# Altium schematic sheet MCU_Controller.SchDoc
size A4; Organization: Q-Tech Design; Address1: Da Nang City; Address2: Viet Nam; DocumentNumber: 2; SheetNumber: 2; SheetTotal: 7
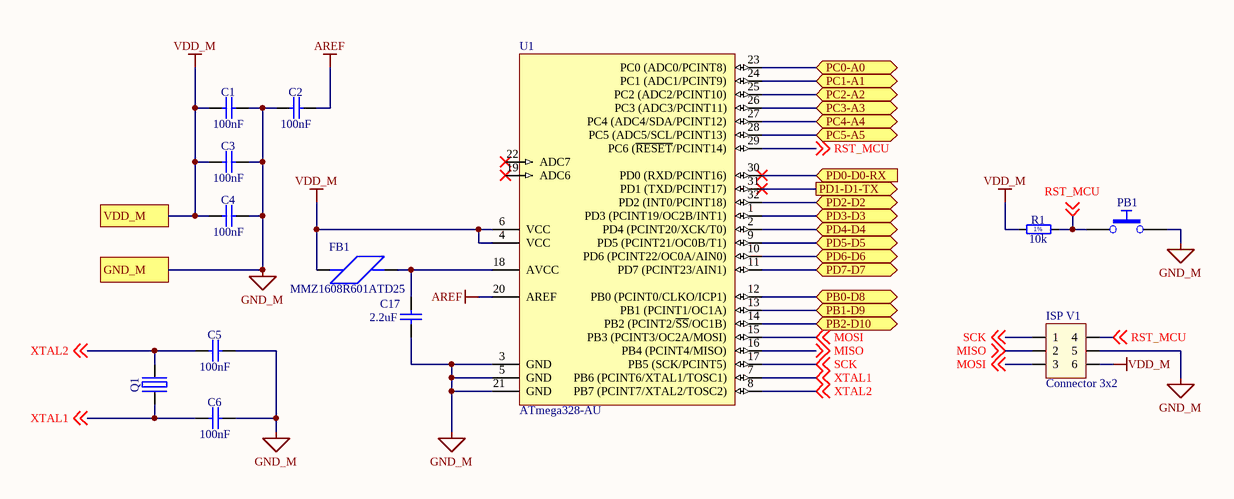
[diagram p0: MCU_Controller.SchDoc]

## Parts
C1  100nF  [CAPC1608X87N]
C2  100nF  [CAPC1608X87N]
C3  100nF  [CAPC1608X87N]
C4  100nF  [CAPC1608X87N]
C5  100nF  [CAPC1608X87N]
C6  100nF  [CAPC1608X87N]
C17  2.2uF  [CAPC1608X87N]
FB1  Manufacturer Part Number: MMZ1608R601ATD25  [Chip_0603]  (hidden comment: Ferrite bead Case 0603)
ISP_V1  Connector 3x2  [JP3x2]
PB1  Push Button  [PB_TYCO_FSMSM]  (value not drawn)
Q1  20MHz  [XTAL_HC-49/U]  (value not drawn)
R1  10k  [RESC1608X55N]
U1  ATmega328-AU  [32A_ATM-M]

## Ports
GND_M, PB0-D8 (bidir), PB1-D9 (bidir), PB2-D10 (bidir), PC0-A0 (bidir), PC1-A1 (bidir), PC2-A2 (bidir), PC3-A3 (bidir), PC4-A4 (bidir), PC5-A5 (bidir), PD0-D0-RX (in), PD1-D1-TX (out), PD2-D2 (bidir), PD3-D3 (bidir), PD4-D4 (bidir), PD5-D5 (bidir), PD6-D6 (bidir), PD7-D7 (bidir), VDD_M

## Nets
AREF: C2.2 U1.20(AREF)
GND_M: C1.2 C2.1 C3.2 C4.2 C5.2 C6.2 C17.1 ISP_V1.5 PB1.2 U1.3(GND) U1.5(GND) U1.21(GND) ; port GND_M
VDD_M: C1.1 C3.1 C4.1 FB1.1 ISP_V1.6 R1.1 U1.4(VCC) U1.6(VCC) ; port VDD_M
MISO: ISP_V1.2 U1.16(PB4_(PCINT4/MISO)) ; off-sheet MISO
MOSI: ISP_V1.3 U1.15(PB3_(PCINT3/OC2A/MOSI)) ; off-sheet MOSI
PB0-D8: U1.12(PB0_(PCINT0/CLKO/ICP1)) ; port PB0-D8
PB1-D9: U1.13(PB1_(PCINT1/OC1A)) ; port PB1-D9
PB2-D10: U1.14(PB2_(PCINT2/~{SS}/OC1B)) ; port PB2-D10
PC0-A0: U1.23(PC0_(ADC0/PCINT8)) ; port PC0-A0
PC1-A1: U1.24(PC1_(ADC1/PCINT9)) ; port PC1-A1
PC2-A2: U1.25(PC2_(ADC2/PCINT10)) ; port PC2-A2
PC3-A3: U1.26(PC3_(ADC3/PCINT11)) ; port PC3-A3
PC4-A4: U1.27(PC4_(ADC4/SDA/PCINT12)) ; port PC4-A4
PC5-A5: U1.28(PC5_(ADC5/SCL/PCINT13)) ; port PC5-A5
PD0-D0-RX: U1.30(PD0_(RXD/PCINT16)) ; port PD0-D0-RX
PD1-D1-TX: U1.31(PD1_(TXD/PCINT17)) ; port PD1-D1-TX
PD2-D2: U1.32(PD2_(INT0/PCINT18)) ; port PD2-D2
PD3-D3: U1.1(PD3_(PCINT19/OC2B/INT1)) ; port PD3-D3
PD4-D4: U1.2(PD4_(PCINT20/XCK/T0)) ; port PD4-D4
PD5-D5: U1.9(PD5_(PCINT21/OC0B/T1)) ; port PD5-D5
PD6-D6: U1.10(PD6_(PCINT22/OC0A/AIN0)) ; port PD6-D6
PD7-D7: U1.11(PD7_(PCINT23/AIN1)) ; port PD7-D7
RST_MCU: ISP_V1.4 PB1.1 R1.2 U1.29(PC6_(~{RESET}/PCINT14)) ; off-sheet RST_MCU
SCK: ISP_V1.1 U1.17(PB5_(SCK/PCINT5)) ; off-sheet SCK
XTAL1: C6.1 Q1.1(OSC1) U1.7(PB6_(PCINT6/XTAL1/TOSC1)) ; off-sheet XTAL1
XTAL2: C5.1 Q1.2(OSC2) U1.8(PB7_(PCINT7/XTAL2/TOSC2)) ; off-sheet XTAL2
NetC17_2: C17.2 FB1.2 U1.18(AVCC)

Not connected (* = marked no-connect by the designer): U1 19(ADC6)* 22(ADC7)*

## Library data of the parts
C1-C4 = CC0603_100NF_50V_10%_X7R: Non-polarised capacitor; Part Description: SMD Multilayer Chip Ceramic Capacitor; Manufacturer: GENERIC; Manufacturer1 Part Number: 223858615649; Voltage: 50V; TC: X7R; Tolerance: ±10%; Table: Capacitors SMD
C5 C6 = CC0603_22PF_50V_5%_NP0: Non-polarised capacitor; Part Description: SMD Multilayer Chip Ceramic Capacitor; Manufacturer: GENERIC; Manufacturer1 Part Number: 223886715229; Value: 22pF; Voltage: 50V; TC: NP0; Tolerance: ±5%; Table: Capacitors SMD
C17 = CC0603_2.2UF_16V_10%_X5R: Non-polarised capacitor; Part Description: SMD Multilayer Chip Ceramic Capacitor; Manufacturer: GENERIC; Manufacturer1 Part Number: CC0603KRX5R7BB225; Voltage: 16V; TC: X5R; Tolerance: ±10%; Table: Capacitors SMD
FB1 = FERRITE_0603
ISP_V1 = JP3x2
PB1 = PB SPST 1NO-2NO: Push-Button Switch SPDT; Part Description: 12VDC 50mA SPST Tactile  Push-Button Switch; Manufacturer: TYCO ELECTRONICS; Manufacturer Part Number: FSMSM or 1437566-3; Table: Switches
Q1 = XTAL_20MHZ_AEL_HC-49/U: Quartz Crystal; Part Description: ±30ppm Quartz Crystal Resonator, HC-49/U Type; Manufacturer: AEL CRYSTALS; Manufacturer Part Number: X20M000000L010; Table: Crystals & Oscillators
R1 = R0603_10K_1%_0.1W_100PPM: Resistor - 1%; Part Description: General Purpose Thick Film Chip Resistor; Manufacturer: GENERIC; Manufacturer1 Part Number: NRC06F1002TRF; Power: 0.1W; TC: ±100ppm/°C; Table: Resistors SMD
U1 = ATmega328-AU: 8-bit AVR Microcontroller, 32KB Flash, 1KB EEPROM, 2KB SRAM, 32-pin TQFP, Industrial Grade (-40°C to 85°C)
